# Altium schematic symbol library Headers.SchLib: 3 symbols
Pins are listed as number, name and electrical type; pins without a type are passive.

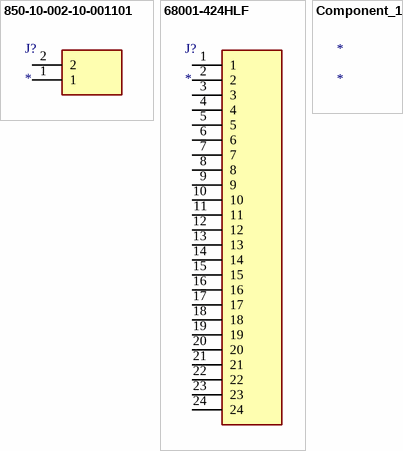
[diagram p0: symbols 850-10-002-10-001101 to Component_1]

## 850-10-002-10-001101
designator J?
Connector; Manufacturer_Name: Preci-Dip; Manufacturer_Part_Number: 850-10-002-10-001101
footprint 8501000210001101
pins: 1, 2

## 68001-424HLF
designator J?
Connector; Manufacturer_Name: Amphenol Communications Solutions; Manufacturer_Part_Number: 68001-424HLF; Description: BergStik
footprint 68001424HLF
pins: 1, 2, 3, 4, 5, 6, 7, 8, 9, 10, 11, 12, 13, 14, 15, 16, 17, 18, 19, 20, 21, 22, 23, 24

## Component_1
designator *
